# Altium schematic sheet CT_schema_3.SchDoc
size 313 x 185 mm
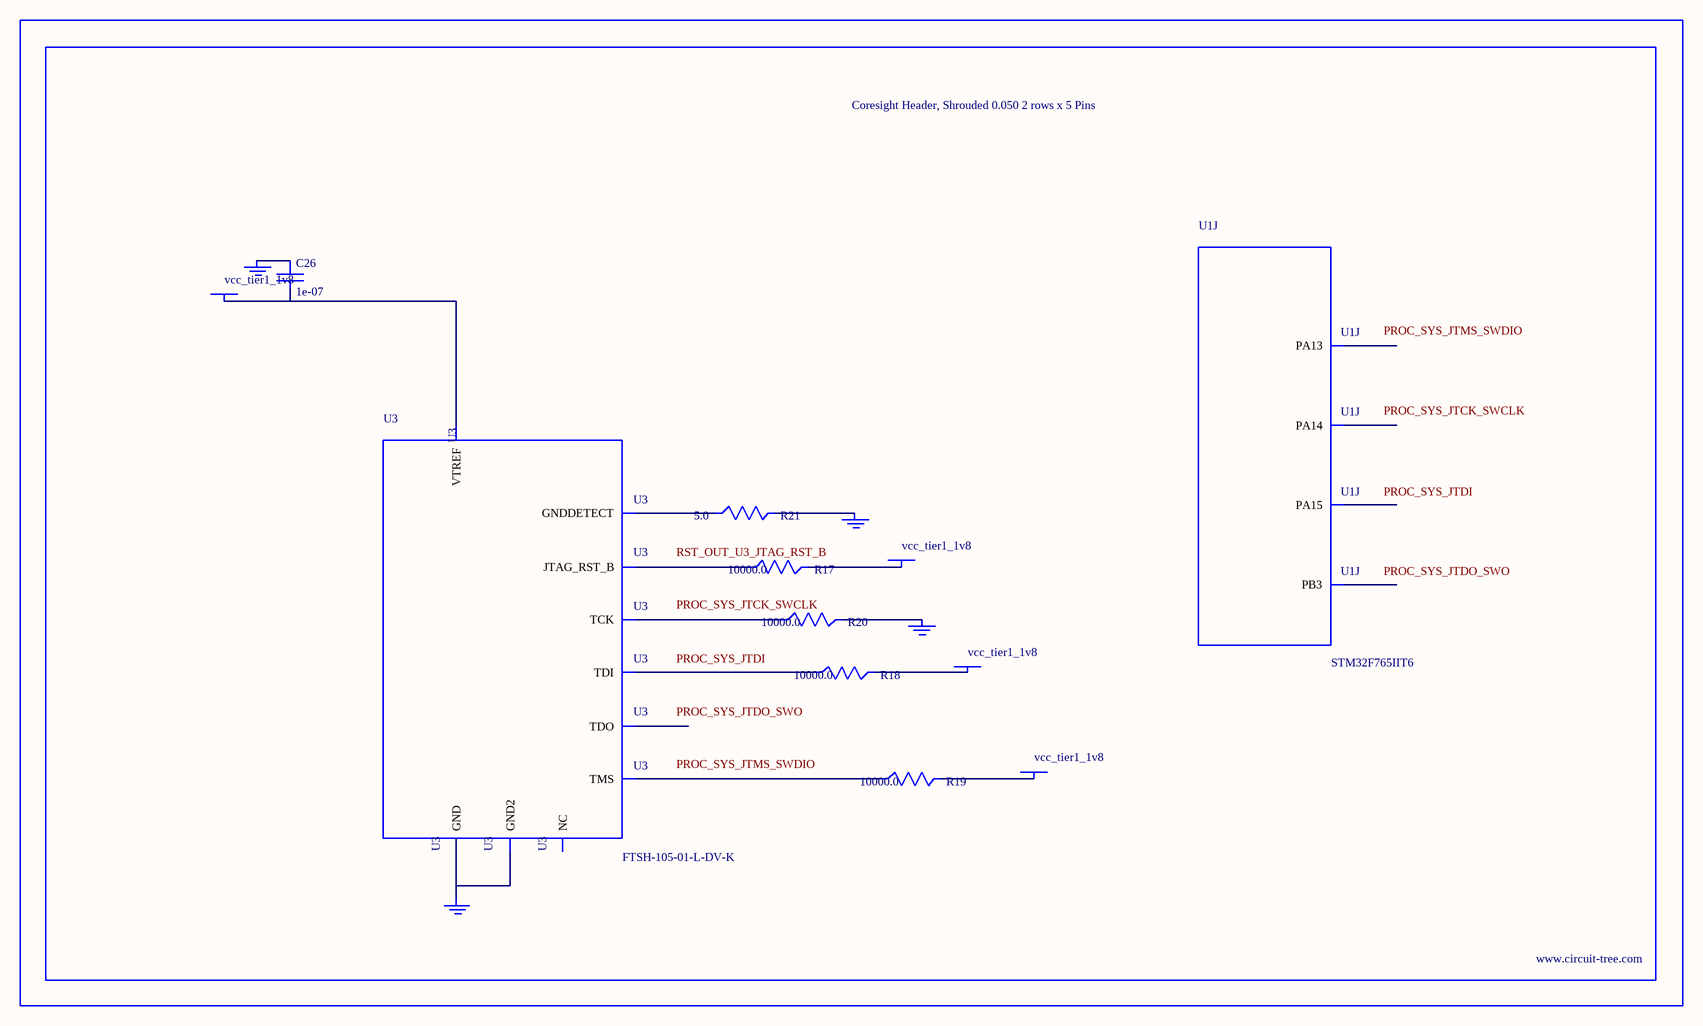
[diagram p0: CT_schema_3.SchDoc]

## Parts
BORDER2  (no value)
C26  1e-07  [C0402]
GND_INSTANCE_2_0  (no value)
GND_INSTANCE_2_1  (no value)
GND_INSTANCE_2_2  (no value)
GND_INSTANCE_2_3  (no value)
POWER_INSTANCE_2_0  vcc_tier1_1v8
POWER_INSTANCE_2_1  vcc_tier1_1v8
POWER_INSTANCE_2_2  vcc_tier1_1v8
POWER_INSTANCE_2_3  vcc_tier1_1v8
R17  10000.0  [R0603]
R18  10000.0  [R0603]
R19  10000.0  [R0603]
R20  10000.0  [R0603]
R21  5.0  [R0603]
U1  STM32F765IIT6  [LQFP176]  (part J of 12)
U3  FTSH-105-01-L-DV-K  [SAMTEC_FTSH-105-01-L-DV-K]

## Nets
NetC26_1: C26.1 GND_INSTANCE_2_0.0(GND)
NetC26_2: C26.2 POWER_INSTANCE_2_0.0(PWR) U3.1(VTREF)
NetGND_INSTANCE_2_1_0: GND_INSTANCE_2_1.0(GND) R20.2
NetGND_INSTANCE_2_2_0: GND_INSTANCE_2_2.0(GND) R21.2
NetGND_INSTANCE_2_3_0: GND_INSTANCE_2_3.0(GND) U3.3(GND) U3.5(GND2)
NetPOWER_INSTANCE_2_1_0: POWER_INSTANCE_2_1.0(PWR) R19.2
NetPOWER_INSTANCE_2_2_0: POWER_INSTANCE_2_2.0(PWR) R18.2
NetPOWER_INSTANCE_2_3_0: POWER_INSTANCE_2_3.0(PWR) R17.2
NetR17_1: R17.1 U3.10(JTAG_RST_B)
NetR18_1: R18.1 U3.8(TDI)
NetR19_1: R19.1 U3.2(TMS)
NetR20_1: R20.1 U3.4(TCK)
NetR21_1: R21.1 U3.9(GNDDETECT)

Not connected (* = marked no-connect by the designer): U1 124(PA13) 137(PA14) 138(PA15) 161(PB3); U3 6(TDO) 7(NC)

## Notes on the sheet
- Labels drawn without touching a wire or pin: PROC_SYS_JTCK_SWCLK, PROC_SYS_JTDI, PROC_SYS_JTDO_SWO, PROC_SYS_JTMS_SWDIO, RST_OUT_U3_JTAG_RST_B

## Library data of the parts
BORDER2 = BORDER_PAGE2
C26 = C0402C104K3RACTU
GND_INSTANCE_2_0-GND_INSTANCE_2_3 = GND
POWER_INSTANCE_2_0-POWER_INSTANCE_2_3 = PWR
R17-R20 = RC0603JR-0710KL
R21 = ERJ-3GEYJ5R1V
